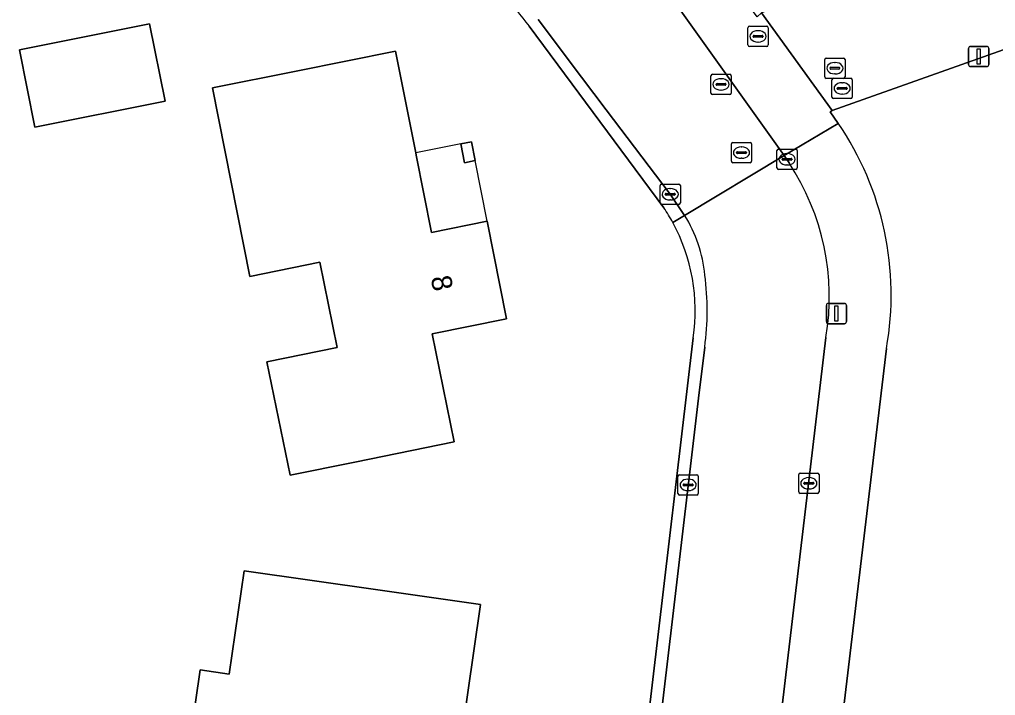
# Model space of a CAD drawing. Extents: x 157648 to 158502, y 379212 to 380938.
# Drawn here: x 158133.21 to 158181.33, y 380169.25 to 380202.59 of the extents above; entities that cross this region are included whole.
import ezdxf

# ---------------------------------------------------------------- set-up
doc = ezdxf.new("R2010")
doc.units = 0
for name, color, linetype in [('IMGEO_Brandkraan', 7, 'Continuous'), ('IMGEO_Erf', 7, 'Continuous'), ('IMGEO_Kolk', 7, 'Continuous'), ('IMGEO_Lichtmast', 7, 'Continuous'), ('IMGEO_Pand', 7, 'Continuous'), ('IMGEO_Pand_nummerreeks', 7, 'Continuous'), ('IMGEO_Pand_overbouw', 7, 'Continuous'), ('IMGEO_Rijbaan_lokaal_open', 7, 'Continuous'), ('IMGEO_Rioolput', 7, 'Continuous'), ('IMGEO_Voetpad_open', 7, 'Continuous')]:
    doc.layers.add(name, color=color, linetype=linetype)

msp = doc.modelspace()

# ---------------------------------------------------------------- linework, layer by layer
at = {"layer": 'IMGEO_Brandkraan'}
for p, q in [((158169.124, 380201.332), (158169.124, 380202.184)), ((158169.199, 380202.258), (158170.051, 380202.258)), ((158170.125, 380202.184), (158170.125, 380201.332)), ((158169.383, 380201.752), (158169.383, 380201.764)), ((158169.821, 380201.715), (158169.423, 380201.715)), ((158169.426, 380201.801), (158169.824, 380201.801)), ((158169.612, 380202.038), (158169.637, 380202.038)), ((158169.867, 380201.764), (158169.867, 380201.752)), ((158170.051, 380201.258), (158169.199, 380201.258)), ((158169.635, 380201.478), (158169.61, 380201.478))]:
    msp.add_line(p, q, dxfattribs=at)
for points in [[(158169.124, 380201.332), (158169.124, 380202.184)], [(158169.199, 380202.258), (158170.051, 380202.258)], [(158170.125, 380202.184), (158170.125, 380201.332)], [(158170.051, 380201.258), (158169.199, 380201.258)]]:
    msp.add_lwpolyline(points, dxfattribs=at)
for centre, radius, start, end in [((158169.201, 380202.182), 0.0765, 91.552, 178.448), ((158169.201, 380202.182), 0.0765, 91.552, 178.448), ((158170.049, 380202.182), 0.0765, 1.552, 88.448), ((158170.049, 380202.182), 0.0765, 1.552, 88.448), ((158169.423, 380201.761), 0.0403, 85.8775, 175.7526), ((158169.42, 380201.751), 0.0366, 178.938, 274.7102), ((158169.824, 380201.758), 0.043, 264.8664, 352.4533), ((158169.828, 380201.763), 0.0386, 1.7309, 96.639), ((158169.201, 380201.334), 0.0765, 181.552, 268.448), ((158169.201, 380201.334), 0.0765, 181.552, 268.448), ((158170.049, 380201.334), 0.0765, 271.552, 358.448), ((158170.049, 380201.334), 0.0765, 271.552, 358.448)]:
    msp.add_arc(centre, radius, start, end, dxfattribs=at)
for centre, major_axis, ratio, start_param, end_param in [((158169.611, 380201.758), (-0.387, 0.002), 0.722429, 4.712389, 7.853982), ((158169.636, 380201.758), (-0.39, 0.002), 0.717154, 1.570796, 4.712389)]:
    msp.add_ellipse(centre, major_axis=major_axis, ratio=ratio, start_param=start_param, end_param=end_param, dxfattribs=at)
at = {"layer": 'IMGEO_Erf'}
for points in [[(158191.21, 380204.483), (158173.283, 380198.101), (158173.173, 380198.029), (158173.576, 380197.468)], [(158164.984, 380193.301), (158158.337, 380202.257)], [(158162.379, 380152.624), (158166.428, 380186.895)], [(158175.95, 380186.37), (158171.741, 380151.076), (158191.586, 380150.755), (158191.589, 380150.781), (158191.991, 380150.866), (158192.313, 380149.335), (158191.672, 380149.199), (158192.511, 380145.079), (158193.188, 380145.224), (158197.79, 380121.862), (158198.344, 380119.047), (158242.386, 380127.715), (158241.844, 380130.469), (158238.043, 380150.085), (158235.002, 380149.49), (158234.201, 380153.591), (158237.242, 380154.185), (158236.166, 380159.436), (158256.938, 380163.375), (158253.955, 380178.433)]]:
    msp.add_lwpolyline(points, dxfattribs=at)
for points in [[(158133.212, 380201.095), (158139.623, 380202.374), (158140.385, 380198.554), (158133.973, 380197.276)], [(158151.747, 380201.019), (158152.745, 380196.015), (158152.768, 380195.899), (158153.528, 380192.091), (158156.271, 380192.637), (158157.228, 380187.831), (158153.555, 380187.082), (158154.64, 380181.762), (158149.741, 380180.764), (158146.551, 380180.114), (158145.41, 380185.714), (158148.865, 380186.419), (158148.01, 380190.619), (158144.575, 380189.919), (158142.721, 380199.22), (158146.844, 380200.042)], [(158154.97, 380196.457), (158155.489, 380196.56), (158155.675, 380195.628), (158155.156, 380195.525)], [(158150.993, 380174.444), (158155.942, 380173.733), (158154.664, 380164.837), (158152.614, 380165.131), (158151.844, 380159.769), (158153.052, 380159.596), (158152.879, 380158.394), (158152.346, 380158.471), (158151.718, 380154.103), (158146.769, 380154.814), (158145.708, 380154.966), (158145.91, 380156.37), (158140.198, 380157.191), (158142.112, 380170.514), (158143.553, 380170.307), (158144.285, 380175.407)]]:
    msp.add_lwpolyline(points, close=True, dxfattribs=at)
for centre, radius, start, end in [((158168.419, 380210.819), 13.227, 202.9283, 220.3392), ((158161.239, 380189.026), 14.949, 349.7652, 34.3834), ((158157.565, 380188.315), 8.939, 28.5181, 33.9011), ((158157.428, 380188.232), 9.099, 351.5504, 28.5678)]:
    msp.add_arc(centre, radius, start, end, dxfattribs=at)
at = {"layer": 'IMGEO_Kolk'}
for p, q in [((158170.554, 380195.269), (158170.554, 380196.121)), ((158170.629, 380196.195), (158171.481, 380196.195)), ((158171.042, 380195.975), (158171.067, 380195.975)), ((158171.555, 380196.121), (158171.555, 380195.269)), ((158170.813, 380195.689), (158170.813, 380195.701)), ((158171.251, 380195.652), (158170.853, 380195.652)), ((158170.856, 380195.738), (158171.254, 380195.738)), ((158171.065, 380195.415), (158171.04, 380195.415)), ((158171.297, 380195.701), (158171.297, 380195.689)), ((158171.481, 380195.195), (158170.629, 380195.195)), ((158164.791, 380193.546), (158164.791, 380194.398)), ((158164.866, 380194.472), (158165.718, 380194.472)), ((158165.792, 380194.398), (158165.792, 380193.546)), ((158165.05, 380193.966), (158165.05, 380193.978)), ((158165.488, 380193.929), (158165.09, 380193.929)), ((158165.093, 380194.015), (158165.491, 380194.015)), ((158165.279, 380194.252), (158165.304, 380194.252)), ((158165.534, 380193.978), (158165.534, 380193.966)), ((158165.718, 380193.472), (158164.866, 380193.472)), ((158165.302, 380193.692), (158165.277, 380193.692)), ((158165.675, 380179.212), (158165.675, 380180.064)), ((158165.75, 380180.138), (158166.602, 380180.138)), ((158166.676, 380180.064), (158166.676, 380179.212)), ((158171.627, 380179.292), (158171.627, 380180.144)), ((158171.702, 380180.218), (158172.554, 380180.218)), ((158172.115, 380179.998), (158172.14, 380179.998)), ((158172.628, 380180.144), (158172.628, 380179.292)), ((158165.934, 380179.632), (158165.934, 380179.644)), ((158166.372, 380179.595), (158165.974, 380179.595)), ((158165.977, 380179.681), (158166.375, 380179.681)), ((158166.163, 380179.918), (158166.188, 380179.918)), ((158166.418, 380179.644), (158166.418, 380179.632)), ((158171.886, 380179.712), (158171.886, 380179.724)), ((158172.324, 380179.675), (158171.926, 380179.675)), ((158171.929, 380179.761), (158172.327, 380179.761)), ((158172.37, 380179.724), (158172.37, 380179.712)), ((158166.602, 380179.138), (158165.75, 380179.138)), ((158166.186, 380179.358), (158166.161, 380179.358)), ((158172.554, 380179.218), (158171.702, 380179.218)), ((158172.138, 380179.438), (158172.113, 380179.438))]:
    msp.add_line(p, q, dxfattribs=at)
for points in [[(158170.554, 380195.269), (158170.554, 380196.121)], [(158170.629, 380196.195), (158171.481, 380196.195)], [(158171.555, 380196.121), (158171.555, 380195.269)], [(158171.481, 380195.195), (158170.629, 380195.195)], [(158164.791, 380193.546), (158164.791, 380194.398)], [(158164.866, 380194.472), (158165.718, 380194.472)], [(158165.792, 380194.398), (158165.792, 380193.546)], [(158165.718, 380193.472), (158164.866, 380193.472)], [(158165.675, 380179.212), (158165.675, 380180.064)], [(158165.75, 380180.138), (158166.602, 380180.138)], [(158166.676, 380180.064), (158166.676, 380179.212)], [(158171.627, 380179.292), (158171.627, 380180.144)], [(158171.702, 380180.218), (158172.554, 380180.218)], [(158172.628, 380180.144), (158172.628, 380179.292)], [(158166.602, 380179.138), (158165.75, 380179.138)], [(158172.554, 380179.218), (158171.702, 380179.218)]]:
    msp.add_lwpolyline(points, dxfattribs=at)
for centre, radius, start, end in [((158170.631, 380196.119), 0.0765, 91.552, 178.448), ((158170.631, 380196.119), 0.0765, 91.552, 178.448), ((158171.479, 380196.119), 0.0765, 1.552, 88.448), ((158171.479, 380196.119), 0.0765, 1.552, 88.448), ((158170.853, 380195.698), 0.0403, 85.8775, 175.7526), ((158170.85, 380195.688), 0.0366, 178.938, 274.7102), ((158171.254, 380195.695), 0.043, 264.8664, 352.4533), ((158171.258, 380195.7), 0.0386, 1.7309, 96.639), ((158170.631, 380195.271), 0.0765, 181.552, 268.448), ((158170.631, 380195.271), 0.0765, 181.552, 268.448), ((158171.479, 380195.271), 0.0765, 271.552, 358.448), ((158171.479, 380195.271), 0.0765, 271.552, 358.448), ((158164.868, 380194.396), 0.0765, 91.552, 178.448), ((158164.868, 380194.396), 0.0765, 91.552, 178.448), ((158165.716, 380194.396), 0.0765, 1.552, 88.448), ((158165.716, 380194.396), 0.0765, 1.552, 88.448), ((158165.09, 380193.975), 0.0403, 85.8775, 175.7526), ((158165.087, 380193.965), 0.0366, 178.938, 274.7102), ((158165.491, 380193.972), 0.043, 264.8664, 352.4533), ((158165.495, 380193.977), 0.0386, 1.7309, 96.639), ((158164.868, 380193.548), 0.0765, 181.552, 268.448), ((158164.868, 380193.548), 0.0765, 181.552, 268.448), ((158165.716, 380193.548), 0.0765, 271.552, 358.448), ((158165.716, 380193.548), 0.0765, 271.552, 358.448), ((158165.752, 380180.062), 0.0765, 91.552, 178.448), ((158165.752, 380180.062), 0.0765, 91.552, 178.448), ((158166.6, 380180.062), 0.0765, 1.552, 88.448), ((158166.6, 380180.062), 0.0765, 1.552, 88.448), ((158171.704, 380180.142), 0.0765, 91.552, 178.448), ((158171.704, 380180.142), 0.0765, 91.552, 178.448), ((158172.552, 380180.142), 0.0765, 1.552, 88.448), ((158172.552, 380180.142), 0.0765, 1.552, 88.448), ((158165.974, 380179.641), 0.0403, 85.8775, 175.7526), ((158165.971, 380179.631), 0.0366, 178.938, 274.7102), ((158166.375, 380179.638), 0.043, 264.8664, 352.4533), ((158166.379, 380179.643), 0.0386, 1.7309, 96.639), ((158171.926, 380179.721), 0.0403, 85.8775, 175.7526), ((158171.923, 380179.711), 0.0366, 178.938, 274.7102), ((158172.327, 380179.718), 0.043, 264.8664, 352.4533), ((158172.331, 380179.723), 0.0386, 1.7309, 96.639), ((158165.752, 380179.214), 0.0765, 181.552, 268.448), ((158165.752, 380179.214), 0.0765, 181.552, 268.448), ((158166.6, 380179.214), 0.0765, 271.552, 358.448), ((158166.6, 380179.214), 0.0765, 271.552, 358.448), ((158171.704, 380179.294), 0.0765, 181.552, 268.448), ((158171.704, 380179.294), 0.0765, 181.552, 268.448), ((158172.552, 380179.294), 0.0765, 271.552, 358.448), ((158172.552, 380179.294), 0.0765, 271.552, 358.448)]:
    msp.add_arc(centre, radius, start, end, dxfattribs=at)
for centre, major_axis, ratio, start_param, end_param in [((158171.041, 380195.695), (-0.387, 0.002), 0.722429, 4.712389, 7.853982), ((158171.066, 380195.695), (-0.39, 0.002), 0.717154, 1.570796, 4.712389), ((158165.278, 380193.972), (-0.387, 0.002), 0.722429, 4.712389, 7.853982), ((158165.303, 380193.972), (-0.39, 0.002), 0.717154, 1.570796, 4.712389), ((158172.114, 380179.718), (-0.387, 0.002), 0.722429, 4.712389, 7.853982), ((158172.139, 380179.718), (-0.39, 0.002), 0.717154, 1.570796, 4.712389), ((158166.162, 380179.638), (-0.387, 0.002), 0.722429, 4.712389, 7.853982), ((158166.187, 380179.638), (-0.39, 0.002), 0.717154, 1.570796, 4.712389)]:
    msp.add_ellipse(centre, major_axis=major_axis, ratio=ratio, start_param=start_param, end_param=end_param, dxfattribs=at)
at = {"layer": 'IMGEO_Lichtmast'}
for p, q in [((158180.004, 380200.364), (158180.004, 380201.164)), ((158180.004, 380201.164), (158180.004, 380200.364)), ((158180.104, 380201.264), (158180.894, 380201.264)), ((158180.894, 380201.264), (158180.104, 380201.264)), ((158180.994, 380201.164), (158180.994, 380200.364)), ((158180.994, 380200.364), (158180.994, 380201.164)), ((158180.894, 380200.264), (158180.104, 380200.264)), ((158180.104, 380200.264), (158180.894, 380200.264)), ((158172.99, 380187.688), (158172.99, 380188.488)), ((158172.99, 380188.488), (158172.99, 380187.688)), ((158173.09, 380188.588), (158173.88, 380188.588)), ((158173.88, 380188.588), (158173.09, 380188.588)), ((158173.98, 380188.488), (158173.98, 380187.688)), ((158173.98, 380187.688), (158173.98, 380188.488)), ((158173.88, 380187.588), (158173.09, 380187.588)), ((158173.09, 380187.588), (158173.88, 380187.588))]:
    msp.add_line(p, q, dxfattribs=at)
for points in [[(158180.424, 380201.139), (158180.574, 380201.139), (158180.574, 380200.389), (158180.424, 380200.389), (158180.424, 380201.139)], [(158173.41, 380188.463), (158173.56, 380188.463), (158173.56, 380187.713), (158173.41, 380187.713), (158173.41, 380188.463)]]:
    msp.add_lwpolyline(points, dxfattribs=at)
for centre, start, end in [((158180.104, 380201.164), 90, 180), ((158180.104, 380201.164), 90, 180), ((158180.894, 380201.164), 0, 90), ((158180.894, 380201.164), 360, 90), ((158180.104, 380200.364), 180, 270), ((158180.104, 380200.364), 180, 270), ((158180.894, 380200.364), 270, 0), ((158180.894, 380200.364), 270, 0), ((158173.09, 380188.488), 90, 180), ((158173.09, 380188.488), 90, 180), ((158173.88, 380188.488), 0, 90), ((158173.88, 380188.488), 360, 90), ((158173.09, 380187.688), 180, 270), ((158173.09, 380187.688), 180, 270), ((158173.88, 380187.688), 270, 0), ((158173.88, 380187.688), 270, 0)]:
    msp.add_arc(centre, 0.1, start, end, dxfattribs=at)
at = {"layer": 'IMGEO_Pand'}
for points in [[(158140.385, 380198.554), (158139.623, 380202.374), (158133.212, 380201.095), (158133.973, 380197.276)], [(158156.271, 380192.637), (158153.528, 380192.091), (158152.768, 380195.899), (158152.745, 380196.015), (158151.747, 380201.019), (158146.844, 380200.042), (158142.721, 380199.22), (158144.575, 380189.919), (158148.01, 380190.619), (158148.865, 380186.419), (158145.41, 380185.714), (158146.551, 380180.114), (158149.741, 380180.764), (158154.64, 380181.762), (158153.555, 380187.082), (158157.228, 380187.831)], [(158154.97, 380196.457), (158155.156, 380195.525), (158155.675, 380195.628), (158155.489, 380196.56)], [(158150.993, 380174.444), (158144.285, 380175.407), (158143.553, 380170.307), (158142.112, 380170.514), (158140.198, 380157.191), (158145.91, 380156.37), (158145.708, 380154.966), (158146.769, 380154.814), (158151.718, 380154.103), (158152.346, 380158.471), (158152.879, 380158.394), (158153.052, 380159.596), (158151.844, 380159.769), (158152.614, 380165.131), (158154.664, 380164.837), (158155.942, 380173.733)]]:
    msp.add_lwpolyline(points, close=True, dxfattribs=at)
at = {"layer": 'IMGEO_Pand_overbouw'}
msp.add_lwpolyline([(158154.97, 380196.457), (158152.745, 380196.015), (158152.768, 380195.899), (158153.528, 380192.091), (158156.271, 380192.637), (158155.675, 380195.628), (158155.156, 380195.525)], close=True, dxfattribs=at)
at = {"layer": 'IMGEO_Rijbaan_lokaal_open'}
for points in [[(158246.209, 380216.392), (158245.754, 380218.66), (158245.234, 380221.247), (158193.686, 380211.088), (158190.532, 380210.271), (158169.797, 380202.917), (158173.283, 380198.101), (158191.21, 380204.483)], [(158158.783, 380202.588), (158160.925, 380199.75), (158162.134, 380198.138), (158165.292, 380193.972), (158166.001, 380192.931), (158170.91, 380195.875), (158165.649, 380203.239), (158163.088, 380206.78)], [(158171.153, 380195.513), (158170.91, 380195.875), (158166.001, 380192.931)], [(158168.642, 380150.615), (158170.139, 380163.244), (158170.812, 380168.737), (158172.97, 380186.906)], [(158166.994, 380186.433), (158166.695, 380183.912), (158165.393, 380172.887), (158164.561, 380165.937), (158162.99, 380152.68)]]:
    msp.add_lwpolyline(points, dxfattribs=at)
for centre, radius, start, end in [((158161.129, 380188.902), 12.008, 350.4339, 33.4072), ((158160.475, 380189.415), 6.55, 4.9942, 32.4698), ((158153.691, 380188.231), 13.424, 352.3008, 7.5056)]:
    msp.add_arc(centre, radius, start, end, dxfattribs=at)
at = {"layer": 'IMGEO_Rioolput'}
for p, q in [((158172.985, 380200.687), (158173.837, 380200.687)), ((158172.91, 380199.761), (158172.91, 380200.613)), ((158173.169, 380200.181), (158173.169, 380200.193)), ((158173.212, 380200.23), (158173.61, 380200.23)), ((158173.398, 380200.467), (158173.423, 380200.467)), ((158173.653, 380200.193), (158173.653, 380200.181)), ((158173.911, 380200.613), (158173.911, 380199.761)), ((158167.298, 380198.964), (158167.298, 380199.816)), ((158167.373, 380199.89), (158168.225, 380199.89)), ((158168.299, 380199.816), (158168.299, 380198.964)), ((158173.837, 380199.687), (158172.985, 380199.687)), ((158173.607, 380200.144), (158173.209, 380200.144)), ((158173.343, 380199.689), (158174.195, 380199.689)), ((158173.421, 380199.907), (158173.396, 380199.907)), ((158167.557, 380199.384), (158167.557, 380199.396)), ((158167.995, 380199.347), (158167.597, 380199.347)), ((158167.6, 380199.433), (158167.998, 380199.433)), ((158167.786, 380199.67), (158167.811, 380199.67)), ((158168.041, 380199.396), (158168.041, 380199.384)), ((158173.268, 380198.763), (158173.268, 380199.615)), ((158173.527, 380199.183), (158173.527, 380199.195)), ((158173.57, 380199.232), (158173.968, 380199.232)), ((158173.756, 380199.469), (158173.781, 380199.469)), ((158174.011, 380199.195), (158174.011, 380199.183)), ((158174.269, 380199.615), (158174.269, 380198.763)), ((158168.225, 380198.89), (158167.373, 380198.89)), ((158167.809, 380199.11), (158167.784, 380199.11)), ((158173.965, 380199.146), (158173.567, 380199.146)), ((158173.779, 380198.909), (158173.754, 380198.909)), ((158174.195, 380198.689), (158173.343, 380198.689)), ((158168.306, 380195.597), (158168.306, 380196.449)), ((158168.381, 380196.523), (158169.233, 380196.523)), ((158169.307, 380196.449), (158169.307, 380195.597)), ((158168.565, 380196.017), (158168.565, 380196.029)), ((158169.003, 380195.98), (158168.605, 380195.98)), ((158168.608, 380196.066), (158169.006, 380196.066)), ((158168.794, 380196.303), (158168.819, 380196.303)), ((158169.049, 380196.029), (158169.049, 380196.017)), ((158169.233, 380195.523), (158168.381, 380195.523)), ((158168.817, 380195.743), (158168.792, 380195.743))]:
    msp.add_line(p, q, dxfattribs=at)
for points in [[(158172.985, 380200.687), (158173.837, 380200.687)], [(158172.91, 380199.761), (158172.91, 380200.613)], [(158173.911, 380200.613), (158173.911, 380199.761)], [(158167.298, 380198.964), (158167.298, 380199.816)], [(158167.373, 380199.89), (158168.225, 380199.89)], [(158168.299, 380199.816), (158168.299, 380198.964)], [(158173.837, 380199.687), (158172.985, 380199.687)], [(158173.343, 380199.689), (158174.195, 380199.689)], [(158173.268, 380198.763), (158173.268, 380199.615)], [(158174.269, 380199.615), (158174.269, 380198.763)], [(158168.225, 380198.89), (158167.373, 380198.89)], [(158174.195, 380198.689), (158173.343, 380198.689)], [(158168.306, 380195.597), (158168.306, 380196.449)], [(158168.381, 380196.523), (158169.233, 380196.523)], [(158169.307, 380196.449), (158169.307, 380195.597)], [(158169.233, 380195.523), (158168.381, 380195.523)]]:
    msp.add_lwpolyline(points, dxfattribs=at)
for centre, radius, start, end in [((158172.987, 380200.611), 0.0765, 91.552, 178.448), ((158172.987, 380200.611), 0.0765, 91.552, 178.448), ((158173.835, 380200.611), 0.0765, 1.552, 88.448), ((158173.835, 380200.611), 0.0765, 1.552, 88.448), ((158173.209, 380200.19), 0.0403, 85.8775, 175.7526), ((158173.206, 380200.18), 0.0366, 178.938, 274.7102), ((158173.61, 380200.187), 0.043, 264.8664, 352.4533), ((158173.614, 380200.192), 0.0386, 1.7309, 96.639), ((158167.375, 380199.814), 0.0765, 91.552, 178.448), ((158167.375, 380199.814), 0.0765, 91.552, 178.448), ((158168.223, 380199.814), 0.0765, 1.552, 88.448), ((158168.223, 380199.814), 0.0765, 1.552, 88.448), ((158172.987, 380199.763), 0.0765, 181.552, 268.448), ((158172.987, 380199.763), 0.0765, 181.552, 268.448), ((158173.345, 380199.613), 0.0765, 91.552, 178.448), ((158173.345, 380199.613), 0.0765, 91.552, 178.448), ((158173.835, 380199.763), 0.0765, 271.552, 358.448), ((158173.835, 380199.763), 0.0765, 271.552, 358.448), ((158174.193, 380199.613), 0.0765, 1.552, 88.448), ((158174.193, 380199.613), 0.0765, 1.552, 88.448), ((158167.597, 380199.393), 0.0403, 85.8775, 175.7526), ((158167.594, 380199.383), 0.0366, 178.938, 274.7102), ((158167.998, 380199.39), 0.043, 264.8664, 352.4533), ((158168.002, 380199.395), 0.0386, 1.7309, 96.639), ((158173.567, 380199.192), 0.0403, 85.8775, 175.7526), ((158173.972, 380199.194), 0.0386, 1.7309, 96.639), ((158167.375, 380198.966), 0.0765, 181.552, 268.448), ((158167.375, 380198.966), 0.0765, 181.552, 268.448), ((158168.223, 380198.966), 0.0765, 271.552, 358.448), ((158168.223, 380198.966), 0.0765, 271.552, 358.448), ((158173.345, 380198.765), 0.0765, 181.552, 268.448), ((158173.345, 380198.765), 0.0765, 181.552, 268.448), ((158173.564, 380199.182), 0.0366, 178.938, 274.7102), ((158173.968, 380199.189), 0.043, 264.8664, 352.4533), ((158174.193, 380198.765), 0.0765, 271.552, 358.448), ((158174.193, 380198.765), 0.0765, 271.552, 358.448), ((158168.383, 380196.447), 0.0765, 91.552, 178.448), ((158168.383, 380196.447), 0.0765, 91.552, 178.448), ((158169.231, 380196.447), 0.0765, 1.552, 88.448), ((158169.231, 380196.447), 0.0765, 1.552, 88.448), ((158168.605, 380196.026), 0.0403, 85.8775, 175.7526), ((158168.602, 380196.016), 0.0366, 178.938, 274.7102), ((158169.006, 380196.023), 0.043, 264.8664, 352.4533), ((158169.01, 380196.028), 0.0386, 1.7309, 96.639), ((158168.383, 380195.599), 0.0765, 181.552, 268.448), ((158168.383, 380195.599), 0.0765, 181.552, 268.448), ((158169.231, 380195.599), 0.0765, 271.552, 358.448), ((158169.231, 380195.599), 0.0765, 271.552, 358.448)]:
    msp.add_arc(centre, radius, start, end, dxfattribs=at)
for centre, major_axis, ratio, start_param, end_param in [((158173.397, 380200.187), (-0.387, 0.002), 0.722429, 4.712389, 7.853982), ((158173.422, 380200.187), (-0.39, 0.002), 0.717154, 1.570796, 4.712389), ((158167.785, 380199.39), (-0.387, 0.002), 0.722429, 4.712389, 7.853982), ((158167.81, 380199.39), (-0.39, 0.002), 0.717154, 1.570796, 4.712389), ((158173.755, 380199.189), (-0.387, 0.002), 0.722429, 4.712389, 7.853982), ((158173.78, 380199.189), (-0.39, 0.002), 0.717154, 1.570796, 4.712389), ((158168.793, 380196.023), (-0.387, 0.002), 0.722429, 4.712389, 7.853982), ((158168.818, 380196.023), (-0.39, 0.002), 0.717154, 1.570796, 4.712389)]:
    msp.add_ellipse(centre, major_axis=major_axis, ratio=ratio, start_param=start_param, end_param=end_param, dxfattribs=at)
at = {"layer": 'IMGEO_Voetpad_open'}
for points in [[(158163.088, 380206.78), (158165.649, 380203.239), (158170.91, 380195.875), (158173.576, 380197.468), (158173.173, 380198.029), (158173.283, 380198.101), (158169.797, 380202.917), (158169.582, 380202.726), (158166.582, 380206.823)], [(158165.419, 380192.583), (158166.001, 380192.931), (158165.292, 380193.972), (158162.134, 380198.138), (158160.925, 380199.75), (158158.783, 380202.588)], [(158158.337, 380202.257), (158164.984, 380193.301)], [(158173.576, 380197.468), (158170.91, 380195.875), (158171.153, 380195.513)], [(158166.001, 380192.931), (158165.419, 380192.583)], [(158166.428, 380186.895), (158162.379, 380152.624)], [(158172.97, 380186.906), (158170.812, 380168.737), (158170.139, 380163.244), (158168.642, 380150.615)], [(158143.542, 380114.501), (158166.68, 380140.8), (158168.979, 380143.487), (158170.949, 380147.011), (158171.741, 380151.076), (158175.95, 380186.37)], [(158166.695, 380183.912), (158166.994, 380186.433)], [(158162.99, 380152.68), (158164.561, 380165.937), (158165.393, 380172.887), (158166.695, 380183.912)]]:
    msp.add_lwpolyline(points, dxfattribs=at)
for centre, radius, start, end in [((158168.419, 380210.819), 13.227, 202.9283, 220.3392), ((158161.239, 380189.026), 14.949, 349.7652, 34.3834), ((158161.129, 380188.902), 12.008, 350.4339, 33.4072), ((158157.565, 380188.315), 8.939, 28.5181, 33.9011), ((158157.428, 380188.232), 9.099, 351.5504, 28.5678), ((158160.475, 380189.415), 6.55, 4.9942, 32.4698), ((158153.691, 380188.231), 13.424, 352.3008, 7.5056)]:
    msp.add_arc(centre, radius, start, end, dxfattribs=at)

# ---------------------------------------------------------------- texts
at = {"layer": 'IMGEO_Pand_nummerreeks'}
msp.add_text('8', height=1, rotation=281.2618, dxfattribs=at).set_placement((158153.479, 380189.86))

doc.saveas('drawing.dxf')
